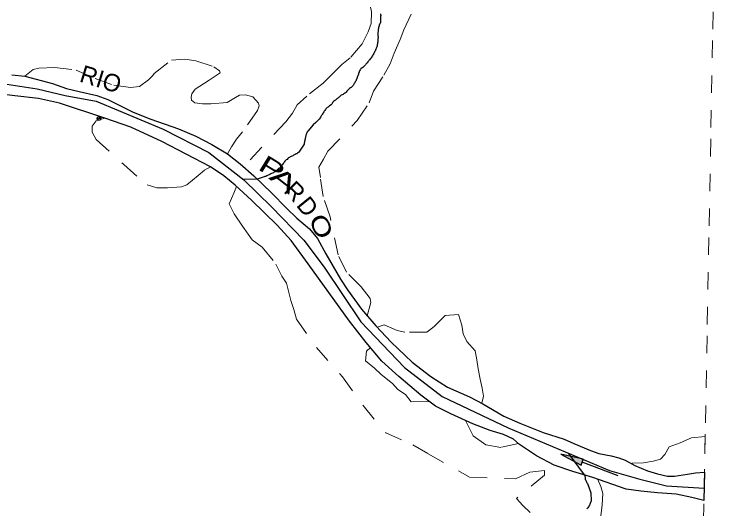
# Model space of a CAD drawing. Extents: x 785.9 to 812.4, y 7674.9 to 7703.1.
# Drawn here: x 807.978 to 812.139, y 7676.663 to 7679.501 of the extents above; entities that cross this region are included whole.
import ezdxf
from ezdxf.enums import TextEntityAlignment as Align

# ---------------------------------------------------------------- set-up
doc = ezdxf.new("R2010")
doc.units = 0
doc.header["$LTSCALE"] = 0.04
doc.header["$PDMODE"] = 32
doc.header["$PDSIZE"] = 0.02
doc.linetypes.add('SHORT_DASHED', pattern=[2.7, 1.5, -1.2])
for name, color, linetype, lineweight in [('10', 7, 'Continuous', 25), ('2', 7, 'Continuous', 25), ('21', 7, 'SHORT_DASHED', 13), ('53', 7, 'SHORT_DASHED', 13), ('55', 7, 'Continuous', 25), ('7', 7, 'Continuous', 25)]:
    doc.layers.add(name, color=color, linetype=linetype, lineweight=lineweight)
doc.layers.add('61', color=7, linetype='Continuous')

msp = doc.modelspace()

# ---------------------------------------------------------------- hatches: boundary and pattern name
at = {"layer": '10'}
msp.add_hatch(color=256, dxfattribs=at).paths.add_polyline_path([(811.118, 7676.9754), (811.2336, 7676.9122), (811.2466, 7676.9467)])

# ---------------------------------------------------------------- linework, layer by layer
msp.add_line((811.448, 7676.8511), (811.2401, 7676.9294), dxfattribs=at)
msp.add_lwpolyline([(811.118, 7676.9754), (811.2336, 7676.9122), (811.2466, 7676.9467)], close=True, dxfattribs=at)
at = {"layer": '2'}
for points in [[(807.9633, 7679.1536), (808.0365, 7679.1461), (808.1959, 7679.1051), (808.2767, 7679.076), (808.3489, 7679.0577), (808.4502, 7679.0361), (808.5137, 7679.0124), (808.5795, 7678.9801), (808.6592, 7678.9402), (808.7615, 7678.8993), (808.921, 7678.8443), (809.0201, 7678.8023), (809.1116, 7678.7538), (809.2021, 7678.701), (809.2743, 7678.6428), (809.354, 7678.5738), (809.4542, 7678.4769)], [(811.9399, 7676.7094), (811.8706, 7676.7258), (811.7812, 7676.7452), (811.6734, 7676.7538), (811.5765, 7676.7624), (811.4935, 7676.7743), (811.3018, 7676.8422), (811.1865, 7676.8756), (811.0798, 7676.9122), (810.9786, 7676.9661), (810.8806, 7677.0318), (810.845, 7677.0609), (810.7879, 7677.0878), (810.7114, 7677.1115), (810.6123, 7677.1503), (810.4852, 7677.2064), (810.3968, 7677.2516), (810.3128, 7677.3141), (810.1868, 7677.4219), (810.0888, 7677.5102), (809.9983, 7677.6169), (809.9035, 7677.7387), (809.6654, 7678.0684), (809.5673, 7678.2031), (809.4876, 7678.2904), (809.339, 7678.4337), (809.2463, 7678.5199), (809.1817, 7678.5738), (809.1052, 7678.6266), (808.8251, 7678.7721), (808.6462, 7678.854), (808.4965, 7678.9057), (808.2357, 7678.9919), (808.1151, 7679.0178), (807.9804, 7679.0329), (807.919, 7679.0404)], [(809.4542, 7678.4769), (809.5415, 7678.3885), (809.5996, 7678.3314), (809.6729, 7678.27), (809.7192, 7678.2139), (809.7677, 7678.1267), (809.8506, 7677.9801), (809.8916, 7677.9187), (809.9723, 7677.8088), (810.0542, 7677.7129), (810.1426, 7677.6191), (810.2632, 7677.5038), (810.3699, 7677.4219), (810.4669, 7677.3605), (810.5929, 7677.3055), (810.6694, 7677.2646), (810.79, 7677.1935), (810.8816, 7677.1536), (811.0152, 7677.1008), (811.137, 7677.062), (811.1919, 7677.0372), (811.2878, 7676.9963), (811.3363, 7676.979), (811.4063, 7676.9661), (811.4505, 7676.9553), (811.4871, 7676.9402), (811.5431, 7676.9101), (811.6153, 7676.8799), (811.6734, 7676.8616), (811.7305, 7676.8486), (811.7715, 7676.8486), (811.8447, 7676.8605), (811.8921, 7676.868), (811.943, 7676.8727), (811.9399, 7676.7094)]]:
    msp.add_lwpolyline(points, dxfattribs=at)
at = {"layer": '21'}
for p, q in [((808.7728, 7679.15), (808.7802, 7679.1613)), ((808.5137, 7679.0124), (808.4502, 7679.0361)), ((810, 7677.5669), (810.0229, 7677.5879)), ((810.3604, 7677.2787), (810.258, 7677.2763)), ((810.8749, 7677.0365), (810.7734, 7677.0143)), ((811.5233, 7676.9208), (811.5272, 7676.9229))]:
    msp.add_line(p, q, dxfattribs=at)
for points in [[(810.0529, 7679.8213), (810.0404, 7679.7789), (810.0229, 7679.7231), (810.0187, 7679.6564), (810.0247, 7679.6128), (810.0222, 7679.5521), (810.0297, 7679.5153), (810.0281, 7679.4499), (810.0105, 7679.4008), (809.9755, 7679.3329), (809.9064, 7679.2514), (809.8592, 7679.2134)], [(810.0529, 7679.8213), (810.0404, 7679.7789), (810.0229, 7679.7231), (810.0187, 7679.6564), (810.0247, 7679.6128), (810.0222, 7679.5521), (810.0297, 7679.5153), (810.0281, 7679.4499), (810.0105, 7679.4008), (809.9755, 7679.3329), (809.9064, 7679.2514), (809.8592, 7679.2134)], [(809.7275, 7678.6236), (809.7535, 7678.6708), (809.7789, 7678.715), (809.948, 7678.8928), (810.0167, 7678.993), (810.0406, 7679.06), (810.1012, 7679.1522), (810.1362, 7679.2172), (810.1592, 7679.2792), (810.1946, 7679.3578), (810.2146, 7679.4131), (810.2602, 7679.5091)], [(808.7802, 7679.1613), (808.8795, 7679.2381), (808.957, 7679.2445), (809.0192, 7679.234), (809.1241, 7679.2009), (809.1564, 7679.1775), (809.1596, 7679.1654), (809.1419, 7679.1541), (809.0975, 7679.1242), (809.0159, 7679.0726), (808.9974, 7679.0459), (808.9933, 7679.0265), (808.9958, 7679.008), (809.0135, 7678.9934), (809.0579, 7678.9878), (809.1064, 7678.9878), (809.2008, 7678.9958), (809.2484, 7679.0249), (809.2702, 7679.0378), (809.3049, 7679.0394), (809.3485, 7679.0281), (809.3792, 7678.991), (809.3849, 7678.9757), (809.3736, 7678.949), (809.2888, 7678.8271), (809.2541, 7678.7851), (809.2242, 7678.7407), (809.2021, 7678.701)], [(808.0365, 7679.1461), (808.0846, 7679.1844), (808.1177, 7679.1923), (808.2077, 7679.1963), (808.3321, 7679.1817), (808.4419, 7679.1328), (808.5478, 7679.0944), (808.6444, 7679.0811), (808.696, 7679.0878), (808.7477, 7679.1261), (808.7728, 7679.15)], [(809.8592, 7679.2134), (809.7987, 7679.1522), (809.7518, 7679.1068), (809.6573, 7679.0323), (809.6023, 7678.9812), (809.5748, 7678.9341), (809.5378, 7678.8845), (809.2932, 7678.6264)], [(809.8592, 7679.2134), (809.7987, 7679.1522), (809.7518, 7679.1068), (809.6573, 7679.0323), (809.6023, 7678.9812), (809.5748, 7678.9341), (809.5378, 7678.8845), (809.2932, 7678.6264)], [(808.4965, 7678.9057), (808.448, 7678.8899), (808.4243, 7678.8594), (808.4237, 7678.8251), (808.4468, 7678.7822), (808.6055, 7678.6389), (808.7394, 7678.5218), (808.7967, 7678.5056), (808.8571, 7678.5056), (808.9375, 7678.5106), (808.9674, 7678.5225), (809.0334, 7678.5766), (809.0695, 7678.6065), (809.1052, 7678.6266)], [(810.0046, 7677.7709), (810.0254, 7677.8459), (810.0221, 7677.8701), (809.97, 7677.9367), (809.8851, 7678.0217), (809.8372, 7678.1208), (809.7922, 7678.3382), (809.7522, 7678.4556), (809.7356, 7678.5639), (809.7275, 7678.6236)], [(809.2537, 7678.5131), (809.2385, 7678.4752), (809.2109, 7678.4127), (809.2402, 7678.3568), (809.2882, 7678.2849), (809.3207, 7678.2386), (809.3445, 7678.207), (809.4008, 7678.165), (809.4804, 7678.066), (809.5138, 7677.9982), (809.5404, 7677.9577), (809.5504, 7677.9188), (809.5665, 7677.8587), (809.5826, 7677.8067), (809.5977, 7677.7503), (809.7129, 7677.5887), (809.8622, 7677.4198), (809.9816, 7677.2541), (810.1114, 7677.0982), (810.2664, 7677.0293), (810.3557, 7676.9772), (810.5935, 7676.8429), (810.8568, 7676.8332), (810.9389, 7676.8728), (811.0247, 7676.8824), (811.0245, 7676.8558), (810.8633, 7676.7213), (810.8999, 7676.6802), (810.9416, 7676.6396)], [(810.6627, 7677.2682), (810.6736, 7677.3086), (810.6655, 7677.355), (810.6541, 7677.4071), (810.6419, 7677.4648), (810.6346, 7677.5177), (810.6248, 7677.5698), (810.5768, 7677.6227), (810.5556, 7677.6667), (810.5483, 7677.7171), (810.5296, 7677.7774), (810.4531, 7677.7717), (810.3888, 7677.7092), (810.3482, 7677.6756), (810.222, 7677.6764), (810.1765, 7677.6862), (810.1024, 7677.7179), (810.0615, 7677.7051)], [(810.258, 7677.2763), (810.2254, 7677.3181), (810.1813, 7677.346), (810.1511, 7677.3809), (810.086, 7677.4321), (810.0465, 7677.4693), (809.9954, 7677.5111), (810, 7677.5669)], [(810.7734, 7677.0143), (810.6874, 7677.0282), (810.613, 7677.0817), (810.5703, 7677.1688)], [(811.5272, 7676.9229), (811.5934, 7676.9254), (811.6477, 7676.9345), (811.6897, 7676.9474), (811.7149, 7676.9743), (811.7406, 7677.0182), (811.8042, 7677.0404), (811.8687, 7677.0689), (811.9468, 7677.0774), (811.943, 7676.8728)], [(811.3457, 7676.6062), (811.356, 7676.6852), (811.3589, 7676.7497), (811.3468, 7676.79), (811.3278, 7676.833)]]:
    msp.add_lwpolyline(points, dxfattribs=at)
for p in [(808.4615, 7678.903), (808.4653, 7678.9036)]:
    msp.add_point(p, dxfattribs=at)
at = {"layer": '53'}
msp.add_lwpolyline([(811.9059, 7674.8946), (811.9165, 7675.4598), (811.9271, 7676.0251), (811.9377, 7676.5903), (811.9483, 7677.1556), (811.9589, 7677.7208), (811.9695, 7678.2861), (811.9801, 7678.8513), (811.9907, 7679.4165), (812.0013, 7679.9818), (812.0119, 7680.547), (812.0225, 7681.1123), (812.0331, 7681.6775), (812.0437, 7682.2428), (812.0543, 7682.808), (812.0648, 7683.3732), (812.0754, 7683.9385), (812.086, 7684.5037), (812.0966, 7685.069), (812.1071, 7685.6342), (812.1177, 7686.1995), (812.1283, 7686.7647), (812.1388, 7687.3299)], dxfattribs=at)
at = {"layer": '55'}
for p, q in [((809.3719, 7678.5551), (809.2908, 7678.554)), ((811.2528, 7676.8564), (811.1625, 7676.981))]:
    msp.add_line(p, q, dxfattribs=at)
msp.add_lwpolyline([(807.8579, 7679.1121), (808.108, 7679.0736), (808.2683, 7679.0351), (808.4478, 7679.0031), (808.8325, 7678.8427), (809.0954, 7678.7079), (809.2951, 7678.5507), (809.4554, 7678.3967), (809.6414, 7678.2042), (809.7568, 7678.0502), (809.9684, 7677.7358), (810.2184, 7677.4728), (810.4364, 7677.306), (810.8147, 7677.1263), (811.3982, 7676.8825), (811.5714, 7676.8312), (811.7252, 7676.7927), (811.9413, 7676.7797)], dxfattribs=at)
at = {"layer": '7'}
for points in [[(810.081, 7679.5055), (810.0818, 7679.4999), (810.0826, 7679.4942), (810.0818, 7679.4885), (810.0818, 7679.4602), (810.081, 7679.4545), (810.0786, 7679.4497), (810.0762, 7679.4448), (810.0745, 7679.44), (810.0729, 7679.4351), (810.0697, 7679.4254), (810.0697, 7679.4198), (810.0681, 7679.4141), (810.0673, 7679.4084), (810.0656, 7679.3955), (810.0664, 7679.3898), (810.0664, 7679.3785), (810.0673, 7679.372), (810.0673, 7679.3664)], [(810.0673, 7679.3664), (810.0664, 7679.3607), (810.0664, 7679.3494), (810.0656, 7679.3429), (810.0648, 7679.3372), (810.064, 7679.3316), (810.0624, 7679.3267), (810.0616, 7679.321), (810.06, 7679.3154), (810.0584, 7679.3105), (810.0567, 7679.3057), (810.0543, 7679.3008), (810.0519, 7679.296), (810.0503, 7679.2911), (810.047, 7679.2862), (810.0454, 7679.2814), (810.0422, 7679.2765), (810.0397, 7679.2717), (810.0373, 7679.2668), (810.0341, 7679.262), (810.0308, 7679.2571), (810.0276, 7679.2523), (810.0244, 7679.2482), (810.0179, 7679.2401), (810.0147, 7679.2361), (810.0114, 7679.232), (810.0082, 7679.228), (810.0041, 7679.2239), (810.0009, 7679.2199), (809.9977, 7679.2159), (809.9944, 7679.2118), (809.9912, 7679.2078), (809.9872, 7679.2037), (809.9831, 7679.2005), (809.9791, 7679.1972), (809.971, 7679.1908), (809.9661, 7679.1875), (809.9637, 7679.1827), (809.9613, 7679.1778), (809.9596, 7679.173), (809.958, 7679.1681), (809.9556, 7679.1633), (809.954, 7679.1584), (809.9507, 7679.1487), (809.9483, 7679.1438), (809.9451, 7679.1333), (809.9418, 7679.1236), (809.9394, 7679.1188), (809.9362, 7679.1139), (809.9337, 7679.109), (809.9305, 7679.1042), (809.9248, 7679.0921), (809.92, 7679.0888), (809.9159, 7679.0856), (809.9119, 7679.0823), (809.9079, 7679.0791), (809.9038, 7679.0751), (809.8998, 7679.0718), (809.8876, 7679.0597), (809.8836, 7679.0556), (809.8795, 7679.0516), (809.8755, 7679.0484), (809.8706, 7679.0451), (809.8666, 7679.0419), (809.8617, 7679.0386), (809.8561, 7679.037), (809.852, 7679.033), (809.848, 7679.0297), (809.8439, 7679.0265), (809.8391, 7679.0233), (809.835, 7679.0192), (809.831, 7679.016), (809.8269, 7679.0128), (809.8229, 7679.0095), (809.818, 7679.0063), (809.814, 7679.003), (809.8059, 7678.995), (809.8043, 7678.9901), (809.8011, 7678.9861), (809.797, 7678.982), (809.7889, 7678.9755), (809.7849, 7678.9723), (809.78, 7678.9691), (809.7752, 7678.9658), (809.7711, 7678.9626), (809.7679, 7678.9585), (809.7646, 7678.9545), (809.7614, 7678.9496), (809.7582, 7678.9456), (809.7549, 7678.9416), (809.7525, 7678.9367), (809.7493, 7678.9318), (809.7468, 7678.927), (809.7436, 7678.9229), (809.7404, 7678.9189), (809.7387, 7678.914), (809.7355, 7678.9092), (809.7293, 7678.8994), (809.7177, 7678.8881), (809.7096, 7678.8801), (809.6934, 7678.8679)], [(809.6934, 7678.8679), (809.6627, 7678.8315), (809.6603, 7678.8267), (809.6578, 7678.8218), (809.6562, 7678.8169), (809.6546, 7678.8121), (809.653, 7678.8072), (809.6514, 7678.8024), (809.6497, 7678.7975), (809.6481, 7678.7886), (809.6478, 7678.787), (809.6475, 7678.7854), (809.6473, 7678.7838), (809.647, 7678.7823), (809.6467, 7678.7807), (809.6464, 7678.7791), (809.6461, 7678.7775), (809.6458, 7678.7759), (809.6455, 7678.7743), (809.6452, 7678.7727), (809.6449, 7678.7711), (809.6446, 7678.7695), (809.6444, 7678.7679), (809.6441, 7678.7663), (809.6438, 7678.7647), (809.6435, 7678.7631), (809.6432, 7678.7616), (809.6429, 7678.76), (809.6426, 7678.7584), (809.6423, 7678.7568), (809.642, 7678.7552), (809.6158, 7678.7166), (809.6093, 7678.7077), (809.6052, 7678.7045), (809.6012, 7678.7012), (809.5963, 7678.6996), (809.5915, 7678.6972), (809.5866, 7678.694), (809.5818, 7678.6923), (809.5769, 7678.6891), (809.5721, 7678.6875), (809.5672, 7678.6851), (809.5624, 7678.6826), (809.5575, 7678.6794), (809.5526, 7678.677), (809.5486, 7678.6729), (809.5446, 7678.6689), (809.5397, 7678.6656), (809.5357, 7678.6616), (809.5324, 7678.6575), (809.5284, 7678.6535), (809.5251, 7678.6486), (809.5219, 7678.6446), (809.5187, 7678.6397), (809.5154, 7678.6349), (809.5114, 7678.6308), (809.5081, 7678.626), (809.5041, 7678.6219), (809.5, 7678.6187), (809.496, 7678.6155), (809.492, 7678.6114), (809.4879, 7678.6082), (809.4839, 7678.6041), (809.479, 7678.6009), (809.475, 7678.5977), (809.4709, 7678.5944), (809.4661, 7678.5912), (809.4604, 7678.5896), (809.4555, 7678.588), (809.4507, 7678.5847), (809.4458, 7678.5823), (809.441, 7678.5807), (809.4361, 7678.5774), (809.4288, 7678.5742), (809.4224, 7678.571), (809.4167, 7678.5702), (809.4119, 7678.5677), (809.407, 7678.5661), (809.3719, 7678.5551)], [(811.2528, 7676.8564), (811.2567, 7676.8402), (811.2567, 7676.8386), (811.2567, 7676.837), (811.2567, 7676.8354), (811.2567, 7676.8345), (811.2583, 7676.8297), (811.2616, 7676.8256), (811.2632, 7676.8208), (811.2648, 7676.8159), (811.268, 7676.8111), (811.2705, 7676.8062), (811.2721, 7676.8014), (811.2761, 7676.7917), (811.2907, 7676.7536), (811.2923, 7676.7067), (811.2899, 7676.7018), (811.2883, 7676.697), (811.2866, 7676.6921), (811.2842, 7676.6873), (811.2818, 7676.6824), (811.2794, 7676.6776), (811.2761, 7676.6727), (811.2729, 7676.6679), (811.2696, 7676.6638), (811.2664, 7676.6598)]]:
    msp.add_lwpolyline(points, dxfattribs=at)

# ---------------------------------------------------------------- texts
at = {"layer": '61'}
for s, rotation, p in [('RIO', 342.846, (808.4593, 7679.0817)), ('R', 315.509, (809.5544, 7678.4491)), ('D', 309.041, (809.6236, 7678.3663))]:
    msp.add_text(s, height=0.1, rotation=rotation, dxfattribs=at).set_placement(p, align=Align.CENTER)
for s, rotation, width, p in [('P', 328.443, 1.6, (809.4315, 7678.577)), ('A', 321.976, 1.75, (809.4961, 7678.5123)), ('O', 296.106, 1.35, (809.696, 7678.2621))]:
    msp.add_text(s, height=0.1, rotation=rotation, dxfattribs=dict(at, width=width)).set_placement(p, align=Align.CENTER)

doc.saveas('drawing.dxf')
